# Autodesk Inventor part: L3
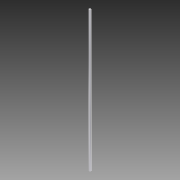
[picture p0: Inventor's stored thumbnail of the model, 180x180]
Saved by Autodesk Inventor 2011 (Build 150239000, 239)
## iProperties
Created: 2014-02
Part Number: L3
Document SubType Name: Modeling
Designer: Evgeny
Density: 1 g/cm^3
Author: Evgeny
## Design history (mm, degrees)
sketch "Эскиз1"
  geometry: C1 r 4 at (0, 0); 1 further point
  constraints: 1 centre point, 1 coincident
  dimensions: "d0" = 8 diameter of C1
extrude "Выдавливание1" new body sketch "Эскиз1" distance "d1" = 596; taper "d2" = 0 deg
feature "Оболочка1" dims "d3" = 1
node "Твердое тело1"
